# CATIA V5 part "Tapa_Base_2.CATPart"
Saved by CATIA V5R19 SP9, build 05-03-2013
Part number: Tapa_Base_2
Bounding box of the stored display mesh (mm): x -25 to 25, y 0 to 154.8, z -2.4 to 3
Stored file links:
  D:\PROGRAMACION\PROYECTOS\DEFCON\CAD\Tapa_Base_2.CATPart
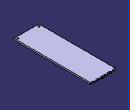
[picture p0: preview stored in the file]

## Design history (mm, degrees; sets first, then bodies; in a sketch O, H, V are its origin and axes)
Set1
  DatumCurve1 to DatumCurve31
  Extract1: ExtractElem face of DatumSurface1
  DatumSurface1 to DatumSurface33
  Extract2: ExtractElem face of DatumSurface2
  Extract3: ExtractElem face of DatumSurface3
  Extract4: ExtractElem face of DatumSurface4
  Extract5: ExtractElem face of DatumSurface5
  Extract6: ExtractElem face of DatumSurface6
  Extract7: ExtractElem face of DatumSurface7
  Extract8: ExtractElem face of DatumSurface8
  Extract9: ExtractElem face of DatumSurface9
  Extract10: ExtractElem face of DatumSurface10
  Extract11: ExtractElem face of DatumSurface11
  Extract12: ExtractElem face of DatumSurface12
  Extract13: ExtractElem face of DatumSurface13
  Extract14: ExtractElem face of DatumSurface14
  Extract15: ExtractElem face of DatumSurface15
  Extract16: ExtractElem face of DatumSurface16
  Extract17: ExtractElem face of DatumSurface17
  Extract18: ExtractElem face of DatumSurface18
  Extract19: ExtractElem face of DatumSurface19
  Extract20: ExtractElem face of DatumSurface20
  Extract21: ExtractElem face of DatumSurface21
  Extract22: ExtractElem face of DatumSurface22
  Extract23: ExtractElem face of DatumSurface23
  Extract24: ExtractElem face of DatumSurface24
  Extract25: ExtractElem face of DatumSurface25
  Extract26: ExtractElem face of DatumSurface26
  Extract27: ExtractElem face of DatumSurface27
  Extract28: ExtractElem face of DatumSurface28
  Extract29: ExtractElem face of DatumSurface29
  Extract30: ExtractElem face of DatumSurface30
  Extract31: ExtractElem face of DatumSurface31
  Extract32: ExtractElem face of DatumSurface32
  Extract33: ExtractElem face of DatumSurface33
  Join1: Elements (Extract33; Extract32; Extract31; Extract30; Extract29; Extract28; Extract27; Extract26; Extract25; Extract24; Extract23; Extract22; Extract21; Extract20; Extract19; Extract18; Extract17; Extract16; Extract15; Extract14; Extract13; Extract12; Extract11; Extract10; Extract9; Extract8; Extract7; Extract6; Extract5; Extract4; Extract3; Extract2; Extract1)
  Offset1: Offset Join1, Length 0.2
  DatumCurve32 to DatumCurve57
Body1 (main body)
  Sketch1 on xy-plane, origin (0, 0, 0), H (1, 0, 0), V (0, 1, 0)
    line L1 (-25, 0) -> (25, 0)
    line L2 (25, 0) -> (25, 154.8)
    line L3 (25, 154.8) -> (-25, 154.8)
    line L4 (-25, 154.8) -> (-25, 0)
    reference intersected line E1 through (0, 0) direction (0, 1) from yz-plane
    reference intersected line E2 through (0, 0) direction (-1, 0) from zx-plane
    length L1 = 50
    length L2 = 154.8
    horizontal: L1 H, L3 H
    vertical: L2 V, L4 V
    symmetry: L4 L2 E1
    coincidence: L1 E2
  Pad1: profile Sketch1, direction (0, 0, 1), length 3
  Split1: SplitPlane Offset1
  Sketch2 on start face of Pad1, origin (0, 0, 0), H (1, 0, 0), V (0, -1, 0)
    projected circle E1 centre (21, -4) radius 2.5 from edge of DatumCurve32
    projected circle E2 centre (-21, -4) radius 2.5 from edge of DatumCurve33
    circle A1 centre (-21, -4) radius 1.7
    point P1 (-21, -4)
    circle A2 centre (21, -4) radius 1.7
    point P2 (21, -4)
    radius A1 = 1.7
    radius A2 = 1.7
    concentricity: P1 E2, P2 E1
  Pocket1: profile Sketch2, direction (0, 0, 1), through (limit type 6)
  Body2
    Sketch3 on face of Pad1 from Sketch1.L1, origin (0, 0, 0), H (1, 0, 0), V (0, 0, 1)
      axis line L1 (0, 39.64) -> (0, -38.36)
      reference projected line E1 (-25, 0) -> (-25, 3) from edge [face of Pad1 from Sketch1.L1 | face of Pad1 from Sketch1.L4]
      reference projected line E2 (25, 0) -> (25, 3) from edge [face of Pad1 from Sketch1.L2 | face of Pad1 from Sketch1.L1]
      arc A1 centre (0, 0) radius 1.6 from (-1.6, 0) to (1.6, 0) ccw
      arc A2 centre (0, 0) radius 2.4 from (-2.4, 0) to (2.4, 0) ccw
      line L2 (-2.4, 0) -> (-1.6, 0)
      point P3 (2.4, 0)
      point P6 (1.6, 0)
      line L3 (1.6, 0) -> (2.4, 0)
      reference projected line E3 (-25, 0) -> (25, 0) from edge [start face of Pad1 | face of Pad1 from Sketch1.L1]
      radius A1 = 1.6
      radius A2 = 2.4
      vertical: L1 V
      symmetry: E1 E2 L1
      horizontal: L2 H, L3 H
      coincidence: L2 P3, L2 P6, L2 L3, L2 E3
    Pad2: profile Sketch3, direction (0, 1, 0), up to face of Split1
    Body3
      Sketch4 on start face of Pad1, origin (0, 0, 0), H (1, 0, 0), V (0, -1, 0)
        projected line E1 (-23, -106) -> (-23, -152) from edge of DatumCurve34
        projected line E2 (23, -106) -> (-23, -106) from edge of DatumCurve35
        projected line E3 (23, -152) -> (23, -106) from edge of DatumCurve36
        projected line E4 (-23, -152) -> (23, -152) from edge of DatumCurve37
        projected line E5 (-23, -100) -> (23, -100) from edge of DatumCurve38
        projected line E6 (23, -100) -> (23, -54) from edge of DatumCurve39
        projected line E7 (23, -54) -> (-23, -54) from edge of DatumCurve40
        projected line E8 (-23, -54) -> (-23, -100) from edge of DatumCurve41
        projected line E9 (23, -2) -> (-23, -2) from edge of DatumCurve42
        projected line E10 (23, -48) -> (23, -2) from edge of DatumCurve43
        projected line E11 (-23, -48) -> (23, -48) from edge of DatumCurve44
        projected line E12 (-23, -2) -> (-23, -48) from edge of DatumCurve45
      Pad3: profile Sketch4, direction (0, 0, -1), length 10
    Remove1: tool Body3
  Assemble1: tool Body2
Body4
  Sketch5 on start face of Pad1, origin (0, 0, 0), H (1, 0, 0), V (0, -1, 0)
    projected line E1 (-23, -2) -> (-23, -48) from edge of DatumCurve46
    projected line E2 (23, -2) -> (-23, -2) from edge of DatumCurve47
    projected line E3 (23, -48) -> (23, -2) from edge of DatumCurve48
    projected line E4 (-23, -48) -> (23, -48) from edge of DatumCurve49
    projected line E5 (23, -54) -> (-23, -54) from edge of DatumCurve50
    projected line E6 (-23, -54) -> (-23, -100) from edge of DatumCurve51
    projected line E7 (23, -100) -> (23, -54) from edge of DatumCurve52
    projected line E8 (-23, -100) -> (23, -100) from edge of DatumCurve53
    projected line E9 (23, -106) -> (-23, -106) from edge of DatumCurve54
    projected line E10 (-23, -106) -> (-23, -152) from edge of DatumCurve55
    projected line E11 (23, -152) -> (23, -106) from edge of DatumCurve56
    projected line E12 (-23, -152) -> (23, -152) from edge of DatumCurve57
    construction line L1 (0, 48) -> (0, -198)
    reference projected line E13 (-25, -154.8) -> (-25, 0) from edge [start face of Pad1 | face of Pad1 from Sketch1.L4]
    reference projected line E14 (25, 0) -> (25, -154.8) from edge [start face of Pad1 | face of Pad1 from Sketch1.L2]
    construction line L2 (-44, -51) -> (46, -51)
    construction line L3 (-45, -103) -> (39, -103)
    point P31 (-22.8, -10)
    line L4 (-22.8, -10) -> (-22, -10)
    line L5 (-22, -10) -> (-22, -40)
    line L6 (-22, -40) -> (-22.8, -40)
    line L7 (-22.8, -40) -> (-22.8, -10)
    point P32 (-22, -10)
    point P33 (-22, -40)
    point P34 (-22.8, -40)
    point P35 (-15, -2.2)
    line L8 (-15, -2.2) -> (-4, -2.2)
    line L9 (-4, -2.2) -> (-4, -3)
    line L10 (-4, -3) -> (-15, -3)
    line L11 (-15, -3) -> (-15, -2.2)
    point P36 (-4, -2.2)
    point P37 (-4, -3)
    point P38 (-15, -3)
    axis line L12 (-42, -25) -> (38, -25)
    point P41 (-4, -47.8)
    point P42 (-15, -47.8)
    line L13 (-15, -47.8) -> (-4, -47.8)
    point P43 (-15, -47)
    line L14 (-15, -47) -> (-15, -47.8)
    point P44 (-4, -47)
    line L15 (-4, -47) -> (-15, -47)
    line L16 (-4, -47.8) -> (-4, -47)
    point P45 (4, -2.2)
    point P46 (15, -2.2)
    line L17 (15, -2.2) -> (4, -2.2)
    point P47 (15, -3)
    line L18 (15, -3) -> (15, -2.2)
    point P48 (4, -3)
    line L19 (4, -3) -> (15, -3)
    line L20 (4, -2.2) -> (4, -3)
    point P49 (22, -10)
    point P50 (22.8, -10)
    line L21 (22.8, -10) -> (22, -10)
    point P51 (22.8, -40)
    line L22 (22.8, -40) -> (22.8, -10)
    point P52 (22, -40)
    line L23 (22, -10) -> (22, -40)
    line L24 (22, -40) -> (22.8, -40)
    point P53 (15, -47.8)
    point P54 (15, -47)
    line L25 (15, -47) -> (15, -47.8)
    point P55 (4, -47)
    line L26 (4, -47) -> (15, -47)
    point P56 (4, -47.8)
    line L27 (15, -47.8) -> (4, -47.8)
    line L28 (4, -47.8) -> (4, -47)
    point P57 (-4, -99.8)
    point P58 (-15, -99.8)
    line L29 (-15, -99.8) -> (-4, -99.8)
    point P59 (-15, -99)
    line L30 (-15, -99) -> (-15, -99.8)
    point P60 (-4, -99)
    line L31 (-4, -99) -> (-15, -99)
    line L32 (-4, -99.8) -> (-4, -99)
    point P61 (4, -99)
    point P62 (4, -99.8)
    line L33 (4, -99.8) -> (4, -99)
    point P63 (15, -99.8)
    line L34 (15, -99.8) -> (4, -99.8)
    point P64 (15, -99)
    line L35 (4, -99) -> (15, -99)
    line L36 (15, -99) -> (15, -99.8)
    point P65 (22, -92)
    point P66 (22.8, -92)
    line L37 (22.8, -92) -> (22, -92)
    point P67 (22, -62)
    line L38 (22, -92) -> (22, -62)
    point P68 (22.8, -62)
    line L39 (22.8, -62) -> (22.8, -92)
    line L40 (22, -62) -> (22.8, -62)
    point P69 (15, -54.2)
    point P70 (15, -55)
    line L41 (15, -55) -> (15, -54.2)
    point P71 (4, -55)
    line L42 (4, -55) -> (15, -55)
    point P72 (4, -54.2)
    line L43 (4, -54.2) -> (4, -55)
    line L44 (15, -54.2) -> (4, -54.2)
    point P73 (-4, -55)
    point P74 (-4, -54.2)
    line L45 (-4, -54.2) -> (-4, -55)
    point P75 (-15, -55)
    line L46 (-4, -55) -> (-15, -55)
    point P76 (-15, -54.2)
    line L47 (-15, -55) -> (-15, -54.2)
    line L48 (-15, -54.2) -> (-4, -54.2)
    point P77 (-22.8, -62)
    point P78 (-22, -62)
    line L49 (-22, -62) -> (-22.8, -62)
    point P79 (-22.8, -92)
    line L50 (-22.8, -62) -> (-22.8, -92)
    point P80 (-22, -92)
    line L51 (-22, -92) -> (-22, -62)
    line L52 (-22.8, -92) -> (-22, -92)
    point P81 (-4, -151.8)
    point P82 (-15, -151.8)
    line L53 (-15, -151.8) -> (-4, -151.8)
    point P83 (-15, -151)
    line L54 (-15, -151) -> (-15, -151.8)
    point P84 (-4, -151)
    line L55 (-4, -151) -> (-15, -151)
    line L56 (-4, -151.8) -> (-4, -151)
    point P85 (4, -151.8)
    point P86 (15, -151.8)
    line L57 (15, -151.8) -> (4, -151.8)
    point P87 (4, -151)
    line L58 (4, -151.8) -> (4, -151)
    point P88 (15, -151)
    line L59 (4, -151) -> (15, -151)
    line L60 (15, -151) -> (15, -151.8)
    point P89 (22.8, -144)
    point P90 (22, -144)
    line L61 (22, -144) -> (22.8, -144)
    point P91 (22, -114)
    line L62 (22, -114) -> (22, -144)
    point P92 (22.8, -114)
    line L63 (22.8, -144) -> (22.8, -114)
    line L64 (22.8, -114) -> (22, -114)
    point P93 (15, -106.2)
    point P94 (15, -107)
    line L65 (15, -107) -> (15, -106.2)
    point P95 (4, -107)
    line L66 (4, -107) -> (15, -107)
    point P96 (4, -106.2)
    line L67 (15, -106.2) -> (4, -106.2)
    line L68 (4, -106.2) -> (4, -107)
    point P97 (-4, -107)
    point P98 (-4, -106.2)
    line L69 (-4, -106.2) -> (-4, -107)
    point P99 (-15, -107)
    line L70 (-4, -107) -> (-15, -107)
    point P100 (-15, -106.2)
    line L71 (-15, -106.2) -> (-4, -106.2)
    line L72 (-15, -107) -> (-15, -106.2)
    point P101 (-22, -114)
    point P102 (-22.8, -114)
    line L73 (-22.8, -114) -> (-22, -114)
    point P103 (-22.8, -144)
    line L74 (-22.8, -144) -> (-22.8, -114)
    point P104 (-22, -144)
    line L75 (-22, -114) -> (-22, -144)
    line L76 (-22, -144) -> (-22.8, -144)
    length L6 = 0.8
    distance L7 E1 = 0.2
    distance L4 L6 = 30
    distance L8 E2 = 0.2
    length L9 = 0.8
    length L8 = 11
    distance L9 L1 = 4
    vertical: L1 V, L5 V, L7 V, L9 V, L11 V
    symmetry: E13 E14 L1, E4 E5 L2, E8 E9 L3, E2 E4 L12, L4 L6 L12, P36 P41 L12, P35 P42 L12, L8 L13 L12, P38 P43 L12, L11 L14 L12, P37 P44 L12, L10 L15 L12, L9 L16 L12, P36 P45 L1, P35 P46 L1, L8 L17 L1, P38 P47 L1, L11 L18 L1, P37 P48 L1, L10 L19 L1, L9 L20 L1, P32 P49 L1, P31 P50 L1, L4 L21 L1, P34 P51 L1, L7 L22 L1, P33 P52 L1, L5 L23 L1, L6 L24 L1, P42 P53 L1, P43 P54 L1, L14 L25 L1, P44 P55 L1, L15 L26 L1, P41 P56 L1, L13 L27 L1, L16 L28 L1, P36 P57 L2, P35 P58 L2, L8 L29 L2, P38 P59 L2, L11 L30 L2, P37 P60 L2, L10 L31 L2, L9 L32 L2, P48 P61 L2, P45 P62 L2, L20 L33 L2, P46 P63 L2, L17 L34 L2, P47 P64 L2, L19 L35 L2, L18 L36 L2, P49 P65 L2, P50 P66 L2, L21 L37 L2, P52 P67 L2, L23 L38 L2, P51 P68 L2, L22 L39 L2, L24 L40 L2, P53 P69 L2, P54 P70 L2, L25 L41 L2, P55 P71 L2, L26 L42 L2, P56 P72 L2, L28 L43 L2, L27 L44 L2, P44 P73 L2, P41 P74 L2, L16 L45 L2, P43 P75 L2, L15 L46 L2, P42 P76 L2, L14 L47 L2, L13 L48 L2, P34 P77 L2, P33 P78 L2, L6 L49 L2, P31 P79 L2, L7 L50 L2, P32 P80 L2, L5 L51 L2, L4 L52 L2, P74 P81 L3, P76 P82 L3, L48 L53 L3, P75 P83 L3, L47 L54 L3, P73 P84 L3, L46 L55 L3, L45 L56 L3, P72 P85 L3, P69 P86 L3, L44 L57 L3, P71 P87 L3, L43 L58 L3, P70 P88 L3, L42 L59 L3, L41 L60 L3, P68 P89 L3, P67 P90 L3, L40 L61 L3, P65 P91 L3, L38 L62 L3, P66 P92 L3, L39 L63 L3, L37 L64 L3, P63 P93 L3, P64 P94 L3, L36 L65 L3, P61 P95 L3, L35 L66 L3, P62 P96 L3, L34 L67 L3, L33 L68 L3, P60 P97 L3, P57 P98 L3, L32 L69 L3, P59 P99 L3, L31 L70 L3, P58 P100 L3, L29 L71 L3, L30 L72 L3, P80 P101 L3, P79 P102 L3, L52 L73 L3, P77 P103 L3, L50 L74 L3, P78 P104 L3, L51 L75 L3, L49 L76 L3
    horizontal: L2 H, L3 H, L4 H, L6 H, L8 H, L10 H, L12 H
  Pad4: profile Sketch5, direction (0, 0, -1), length 1.5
